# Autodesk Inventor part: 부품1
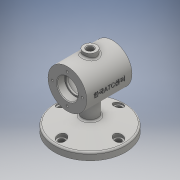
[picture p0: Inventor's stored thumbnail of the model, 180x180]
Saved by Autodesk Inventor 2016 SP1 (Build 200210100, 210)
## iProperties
Created: 2018-12
Part Number: 부품1
Material: 일반
Document SubType Name: Modeling
Designer: basic
Density: 1 g/cm^3
Appearance: 기본값
Author: basic
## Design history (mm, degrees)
sketch "스케치1"
  geometry: C1 r 55 at (0, 0); 1 further point
  constraints: 1 centre point, 1 coincident
  dimensions: "d0" = 110 diameter of C1
extrude "돌출1" new body sketch "스케치1" distance "d1" = 11; taper "d2" = 0 deg
sketch "스케치2"
  geometry: L1 (55, 11)-(-55, 11) reference; L2 (-55, 0)-(55, 0) reference; L3 (-55, 11)-(0, 25.737); L4 (55, 11)-(-55, 11) reference; L5 (0, 11)-(-55, 11); L6 (-55, 11)-(-55, 57.021); L7 (0, 25.737)-(0, 11); 3 further points
  constraints: 8 end point, 3 midpoint, 1 horizontal, 1 point on line, 1 vertical, 1 vertical alignment
  dimensions: "d3" = 75 deg angle of L3 L6; "d4" = 14.73721 distance of L3.end L7.end
revolve "회전1" sketch "스케치2" stored, may be unused: angle "d5" = 90 deg
sketch "스케치3"
  geometry: L1 (55, 11)-(-55, 11) reference; L2 (-55, 0)-(55, 0) reference; L3 (0, 0)-(0, 75); C1 r 30 at (0, 75)
  constraints: 2 end point, 1 centre point, 1 coincident, 1 vertical
  dimensions: "d6" = 75 distance of L3.start L3.end; "d7" = 60 diameter of C1
extrude "돌출2" join sketch "스케치3" stored distance "d8" = 70; taper "d9" = 0 deg
sketch "스케치4"
  geometry: C1 r 30 at (0, 75) reference; C2 r 25 at (0, 75); 1 further point
  constraints: 1 centre point, 1 coincident
  dimensions: "d10" = 50 diameter of C2
extrude "돌출3" cut sketch "스케치4" stored distance "d11" = 40; taper "d12" = 0 deg
node "작업 평면1"
sketch "스케치5"
  geometry: C1 r 12 at (0, 0); 1 further point
  constraints: 1 centre point, 1 coincident
  dimensions: "d14" = 24 diameter of C1
extrude "돌출4" join sketch "스케치5" stored distance "d15" = 40; taper "d16" = 0 deg
hole "구멍1" diameter "d19" = 28; stored, may be unused: countersink angle "d23" = 90 deg, drill point angle "d25" = 0 deg; dims "d17" = 10, "d18" = 10, "d20" = 6, "d21" = 32, "d22" = 12, "d24" = 16.75
hole "구멍2" diameter "d28" = 28; stored, may be unused: countersink angle "d32" = 90 deg, drill point angle "d34" = 0 deg; dims "d26" = 10, "d27" = 10, "d29" = 6, "d30" = 32, "d31" = 12, "d33" = 16.75
sketch "스케치6"
  geometry: C1 r 30 at (0, 0) reference; 2 further points
  constraints: 1 vertical alignment
  dimensions: "d35" = 23 distance of point (0, 23) C1.centre
hole "구멍3" sketch "스케치6" at (0, 23) diameter "d36" = 3.242; stored, may be unused: countersink angle "d40" = 90 deg, drill point angle "d42" = 118 deg; dims "d37" = 8, "d38" = 4, "d39" = 2, "d41" = 10
node "작업 평면2"
node "작업 평면3"
sketch "스케치7"
  geometry: C1 r 10 at (0, 0); 1 further point
  constraints: 1 centre point, 1 coincident
  dimensions: "d47" = 20 diameter of C1
extrude "돌출5" join sketch "스케치7" stored distance "d48" = 40; taper "d49" = 0 deg
sketch "스케치8"
  geometry: C1 r 5 at (0, 0); 1 further point
  constraints: 1 centre point, 1 coincident
  dimensions: "d50" = 10 diameter of C1
extrude "돌출6" cut sketch "스케치8" distance "d51" = 40; taper "d52" = 0 deg
sketch "스케치9"
  geometry: C1 r 4.5 at (-44, 0); 1 further point
  constraints: 1 centre point, 1 horizontal alignment
  dimensions: "d53" = 9 diameter of C1; "d54" = 44 distance of point (0, 0) C1.centre
extrude "돌출7" cut sketch "스케치9" distance "d55" = 18.75; taper "d56" = 0 deg
node "작업 평면4"
sketch "스케치10"
  geometry: C1 r 4.5 at (-44, 0) reference; C2 r 7 at (-44, 0); 1 further point
  constraints: 1 centre point, 1 coincident
  dimensions: "d58" = 14 diameter of C2
extrude "돌출8" cut sketch "스케치10" stored distance "d59" = 18.75; taper "d60" = 0 deg
fillet "모깎기1" dims "d64" = 0.3
fillet "모깎기2" dims "d65" = 3
chamfer "모따기1" distance "d66" = 1; stored, may be unused: second distance "d67" = 2, angle "d68" = 45 deg
fillet "모깎기3" dims "d69" = 3
fillet "모깎기4" dims "d70" = 3
node "작업 평면5"
sketch "스케치11"
  geometry: L1 (-35, 105)-(35, 105) reference; L2 (-35, 105)-(-35, 45) reference; 2 further points
  constraints: 1 other
  dimensions: "d72" = 30 distance from line of L1 point (0, 75); "d73" = 35 distance from line of L2 point (0, 75)
feature "엠보싱1" sketch "스케치11" dims "d6" = 75, "d7" = 60, "d74" = 0.5, "d75" = 0
node "솔리드1"
pattern_circular "원형 패턴1" dims angle "d44" = 360 deg
mirror "대칭1"
pattern_circular "원형 패턴2" dims angle "d62" = 360 deg
node "투영된 루프1"
node "투영된 루프2"
node "투영된 루프3"
other parameters: "d13" = -11, "d46" = -112, "d71" = 40.5
